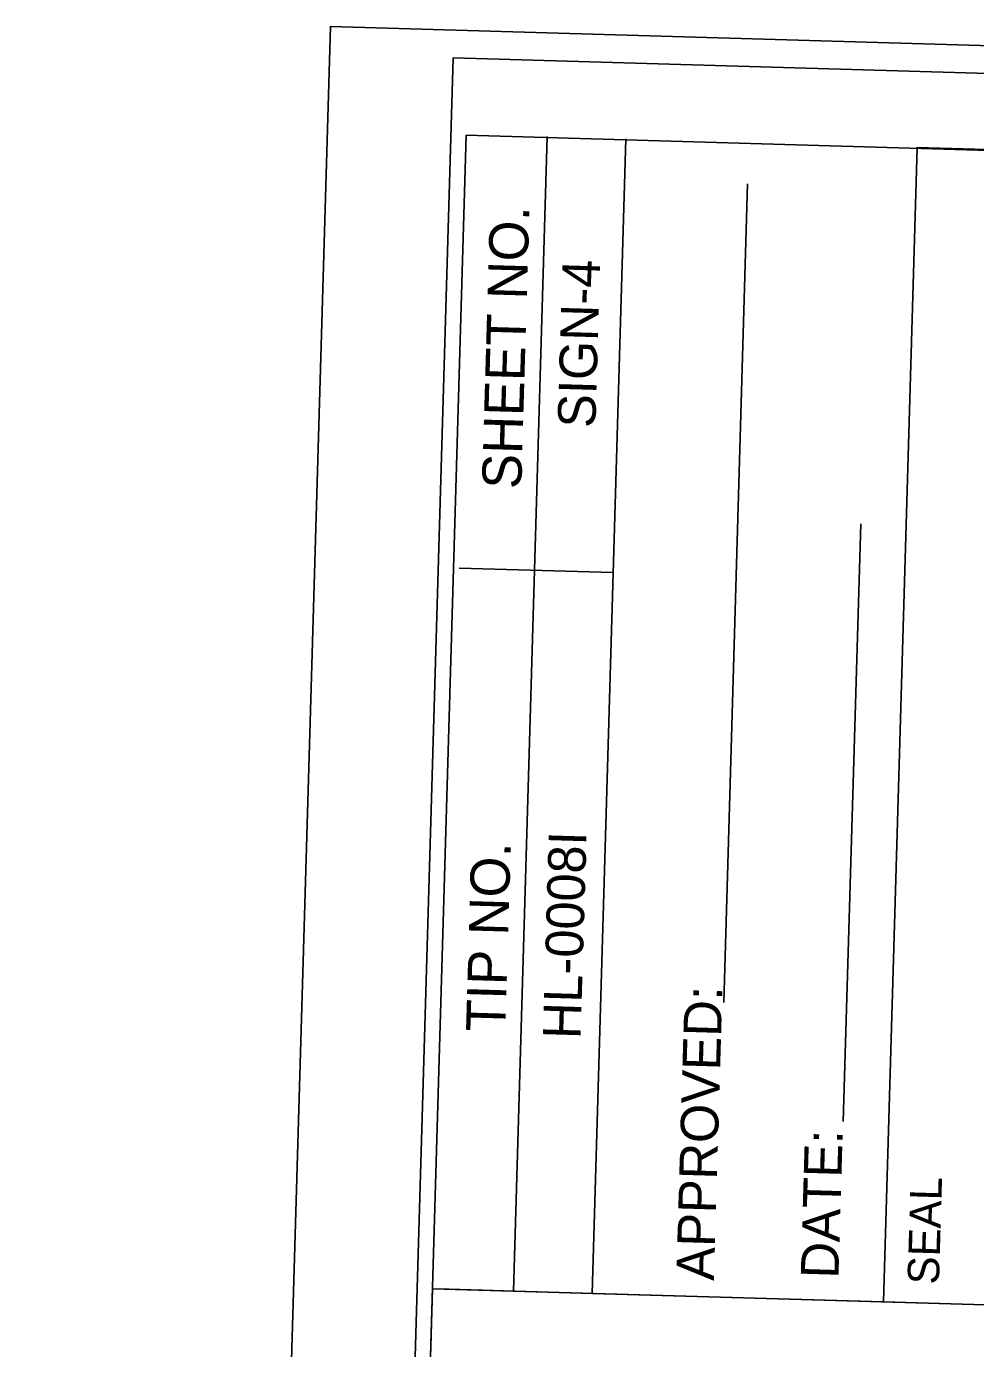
# Model space of a CAD drawing. Extents: x 2096999 to 2102576, y 682920 to 687015.
# Drawn here: x 2096999.4 to 2097153, y 686627 to 686841 of the extents above; entities that cross this region are included whole.
import ezdxf

# ---------------------------------------------------------------- set-up
doc = ezdxf.new("R2010")
doc.units = 0
for name, color, linetype in [('Default', 7, 'Continuous'), ('Old_Level_10', 7, 'Continuous'), ('Old_Level_2', 7, 'Continuous'), ('Old_Level_4', 7, 'Continuous'), ('Scratch_Level_2', 7, 'Continuous'), ('Sheet Plan CELL', 7, 'Continuous'), ('Sheet Plot Border Inside CELL', 7, 'Continuous'), ('Sheet Plot Border Outside CELL', 7, 'Continuous')]:
    doc.layers.add(name, color=color, linetype=linetype)

msp = doc.modelspace()

# ---------------------------------------------------------------- linework, layer by layer
at = {"layer": 'Default'}
for p, q in [((2097081.66, 686752.99), (2097083.71, 686823.18)), ((2097081.66, 686752.99), (2097083.71, 686823.18)), ((2097090.96, 686635.94), (2097096.44, 686822.8)), ((2097090.96, 686635.94), (2097096.44, 686822.8)), ((2097112.26, 686683.01), (2097116.14, 686815.54)), ((2097112.26, 686683.01), (2097116.14, 686815.54)), ((2097131.61, 686663.76), (2097134.44, 686760.48)), ((2097131.61, 686663.76), (2097134.44, 686760.48)), ((2097094.38, 686752.61), (2097069.44, 686753.34)), ((2097094.38, 686752.61), (2097069.44, 686753.34)), ((2097094.38, 686752.61), (2097069.44, 686753.34)), ((2097094.38, 686752.61), (2097069.44, 686753.34)), ((2097078.23, 686636.31), (2097081.66, 686752.99)), ((2097078.23, 686636.31), (2097081.66, 686752.99)), ((2097090.96, 686635.94), (2097066.03, 686636.67)), ((2097090.96, 686635.94), (2097066.03, 686636.67))]:
    msp.add_line(p, q, dxfattribs=at)
at = {"layer": 'Old_Level_2'}
msp.add_line((2097138.11, 686634.56), (2097090.96, 686635.94), dxfattribs=at)
msp.add_line((2097138.11, 686634.56), (2097090.96, 686635.94), dxfattribs=at)
msp.add_lwpolyline([(2097138.11, 686634.56), (2097143.57, 686821.42), (2097254.9, 686818.17), (2097249.44, 686631.3)], close=True, dxfattribs=at)
msp.add_lwpolyline([(2097138.11, 686634.56), (2097143.57, 686821.42), (2097254.9, 686818.17), (2097249.44, 686631.3)], close=True, dxfattribs=at)
at = {"layer": 'Scratch_Level_2'}
msp.add_lwpolyline([(2097234.32, 685317.78), (2097026.76, 685323.81), (2097058.72, 686423.24), (2097059.31, 686437.01), (2097065.14, 686636.69), (2097214.22, 686632.33), (2097231.8, 686631.82), (2097295.87, 686629.95), (2097298.79, 686729.78), (2098044.58, 686708.09), (2098037.23, 686456.47), (2098110.07, 686454.34), (2098090.85, 685704.42)], close=True, dxfattribs=at)
at = {"layer": 'Sheet Plan CELL'}
msp.add_lwpolyline([(2097070.6, 686823.38), (2097026.77, 685323.98), (2098076.32, 685293.3), (2098120.15, 686792.67)], close=True, dxfattribs=at)
msp.add_lwpolyline([(2097070.6, 686823.38), (2097026.77, 685323.98), (2098076.32, 685293.3), (2098120.15, 686792.67)], close=True, dxfattribs=at)
at = {"layer": 'Sheet Plot Border Inside CELL'}
msp.add_lwpolyline([(2098074.34, 685139.8), (2098123.02, 686805.08), (2097068.48, 686835.92), (2097019.79, 685170.63)], close=True, dxfattribs=at)
msp.add_lwpolyline([(2098074.34, 685139.8), (2098123.02, 686805.08), (2097068.48, 686835.92), (2097019.79, 685170.63)], close=True, dxfattribs=at)
at = {"layer": 'Sheet Plot Border Outside CELL'}
msp.add_lwpolyline([(2098093.96, 685126.22), (2098143.15, 686809.01), (2097048.62, 686841), (2096999.42, 685158.22)], close=True, dxfattribs=at)
msp.add_lwpolyline([(2098093.96, 685126.22), (2098143.15, 686809.01), (2097048.62, 686841), (2096999.42, 685158.22)], close=True, dxfattribs=at)

# ---------------------------------------------------------------- texts
at = {"layer": 'Default'}
for s, height, p in [('SHEET NO.', 6.356, (2097079.49, 686766.07)), ('SHEET NO.', 6.356, (2097079.49, 686766.07)), ('SIGN-4', 6.108, (2097091.49, 686775.97)), ('HL-0008I', 6.108, (2097089.1, 686677.05)), ('TIP NO.', 6.356, (2097076.91, 686678.22)), ('TIP NO.', 6.356, (2097076.91, 686678.22))]:
    msp.add_text(s, height=height, rotation=88.3203, dxfattribs=at).set_placement(p)
at = {"layer": 'Old_Level_10'}
msp.add_text('SEAL', height=5.093, rotation=88.3203, dxfattribs=at).set_placement((2097147.1, 686637.32))
msp.add_text('SEAL', height=5.093, rotation=88.3203, dxfattribs=at).set_placement((2097147.1, 686637.32))
at = {"layer": 'Old_Level_4'}
for s, p in [('APPROVED:', (2097110.68, 686637.95)), ('APPROVED:', (2097110.68, 686637.95)), ('DATE:', (2097130.83, 686638.28)), ('DATE:', (2097130.83, 686638.28))]:
    msp.add_text(s, height=6.108, rotation=88.3203, dxfattribs=at).set_placement(p)

doc.saveas('drawing.dxf')
